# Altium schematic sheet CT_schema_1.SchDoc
size 576 x 540 mm
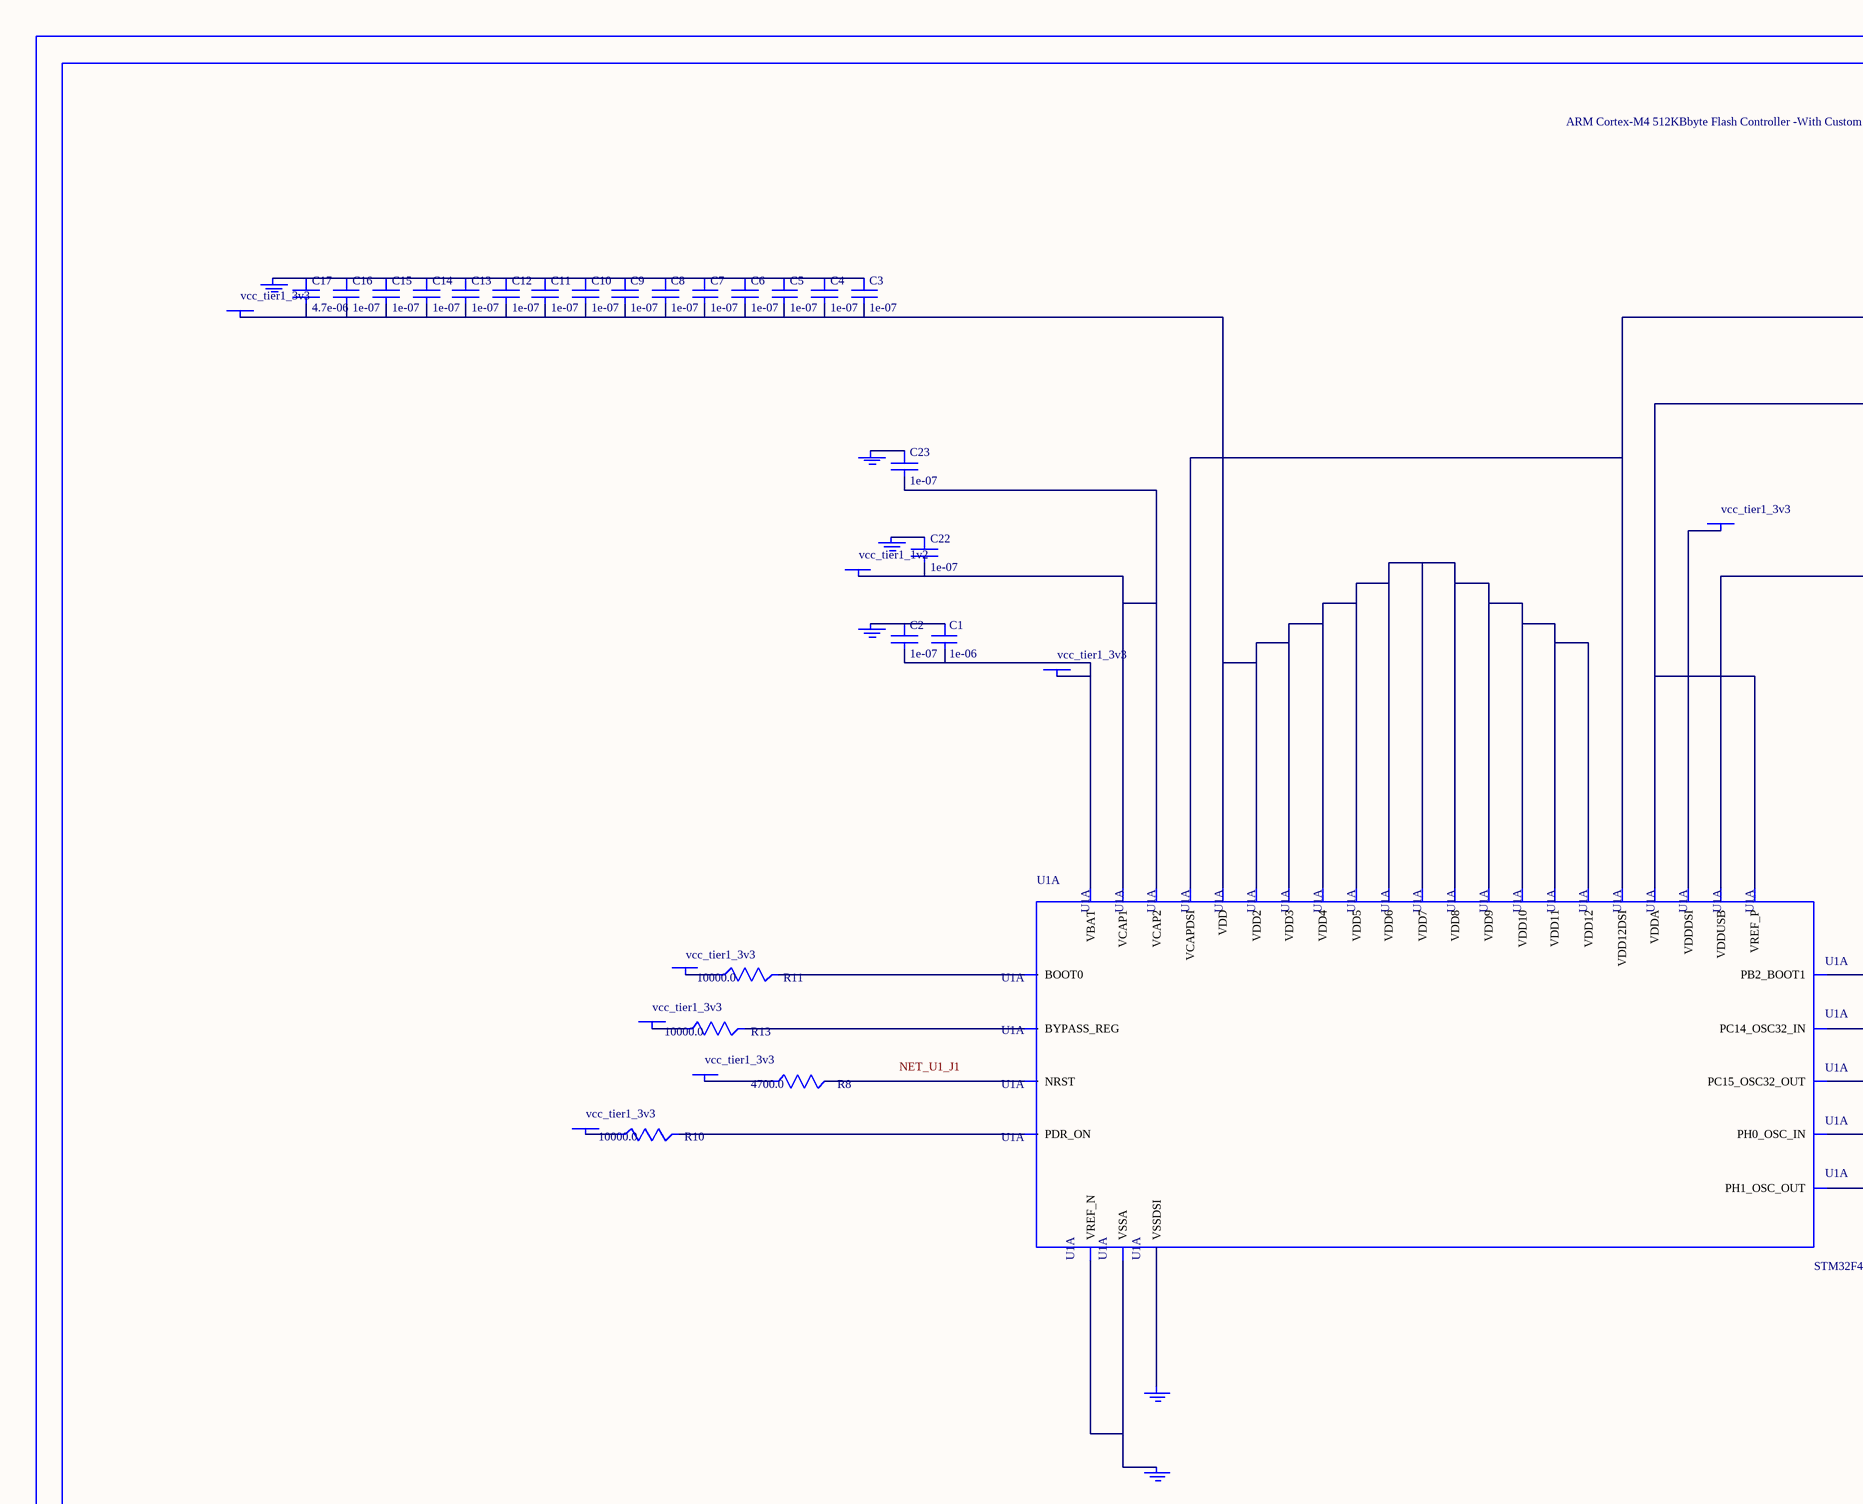
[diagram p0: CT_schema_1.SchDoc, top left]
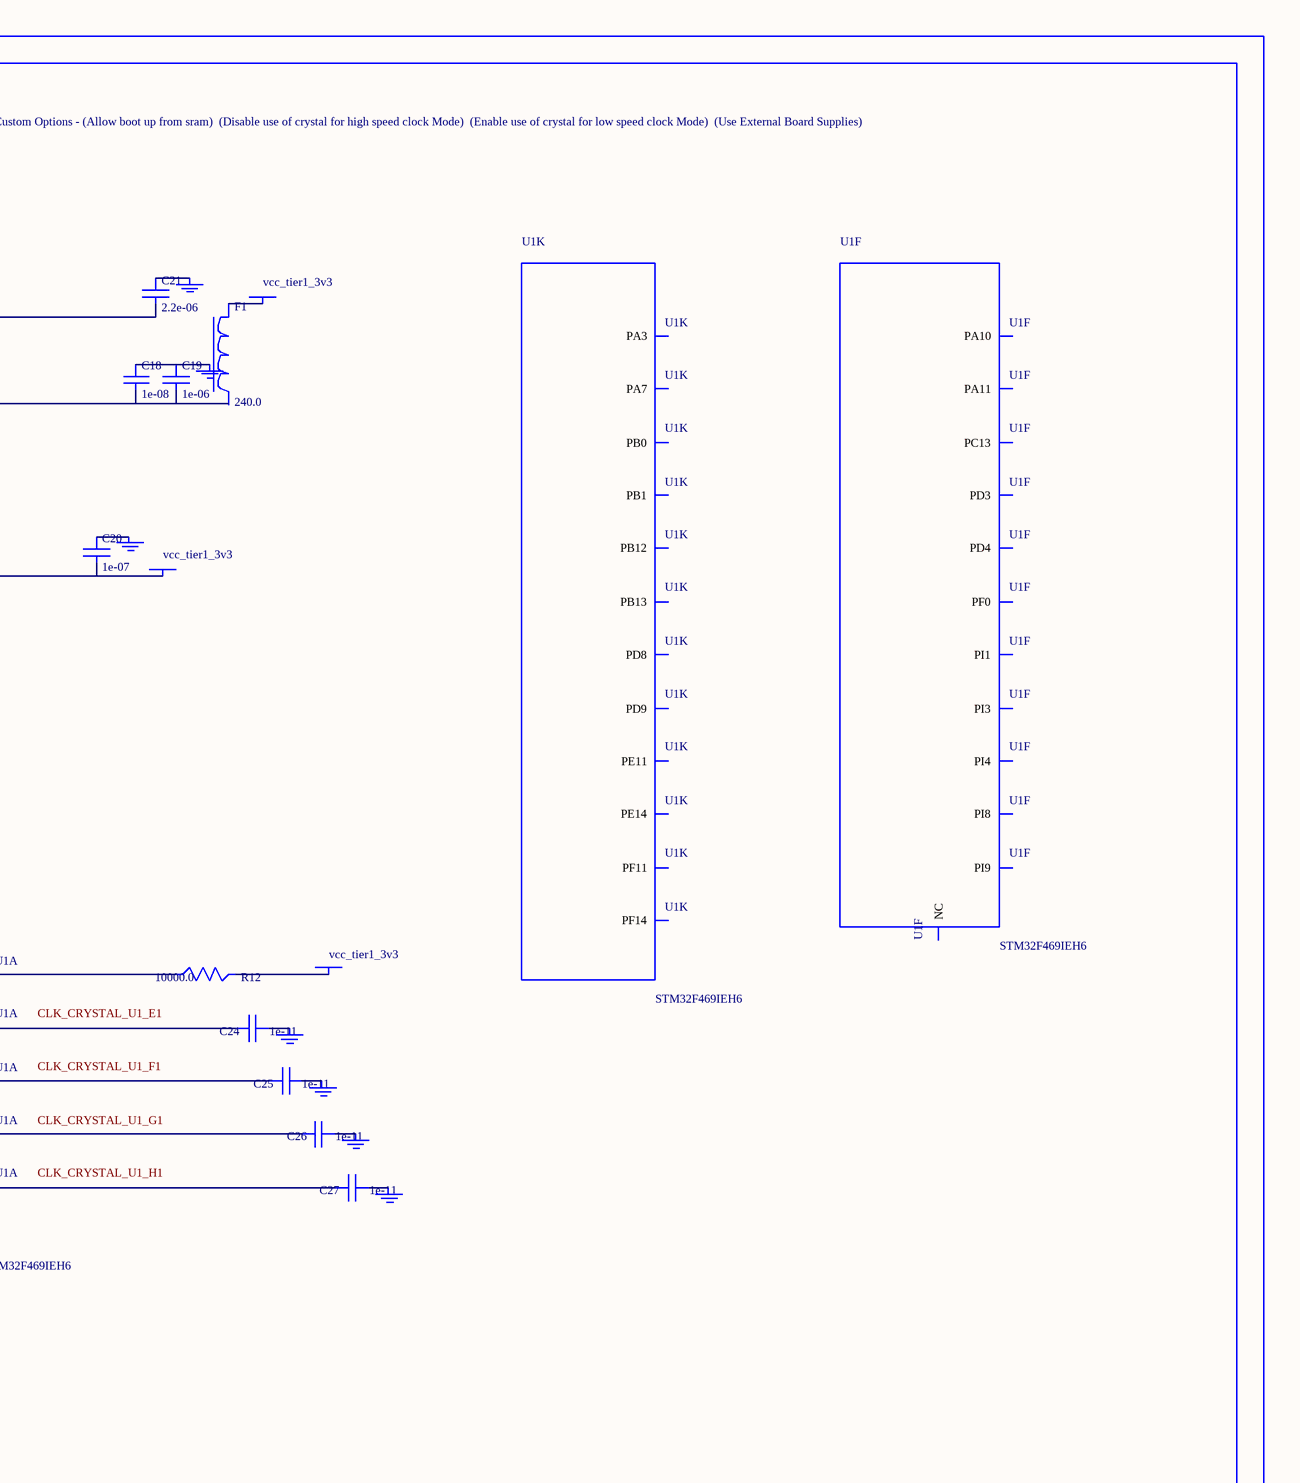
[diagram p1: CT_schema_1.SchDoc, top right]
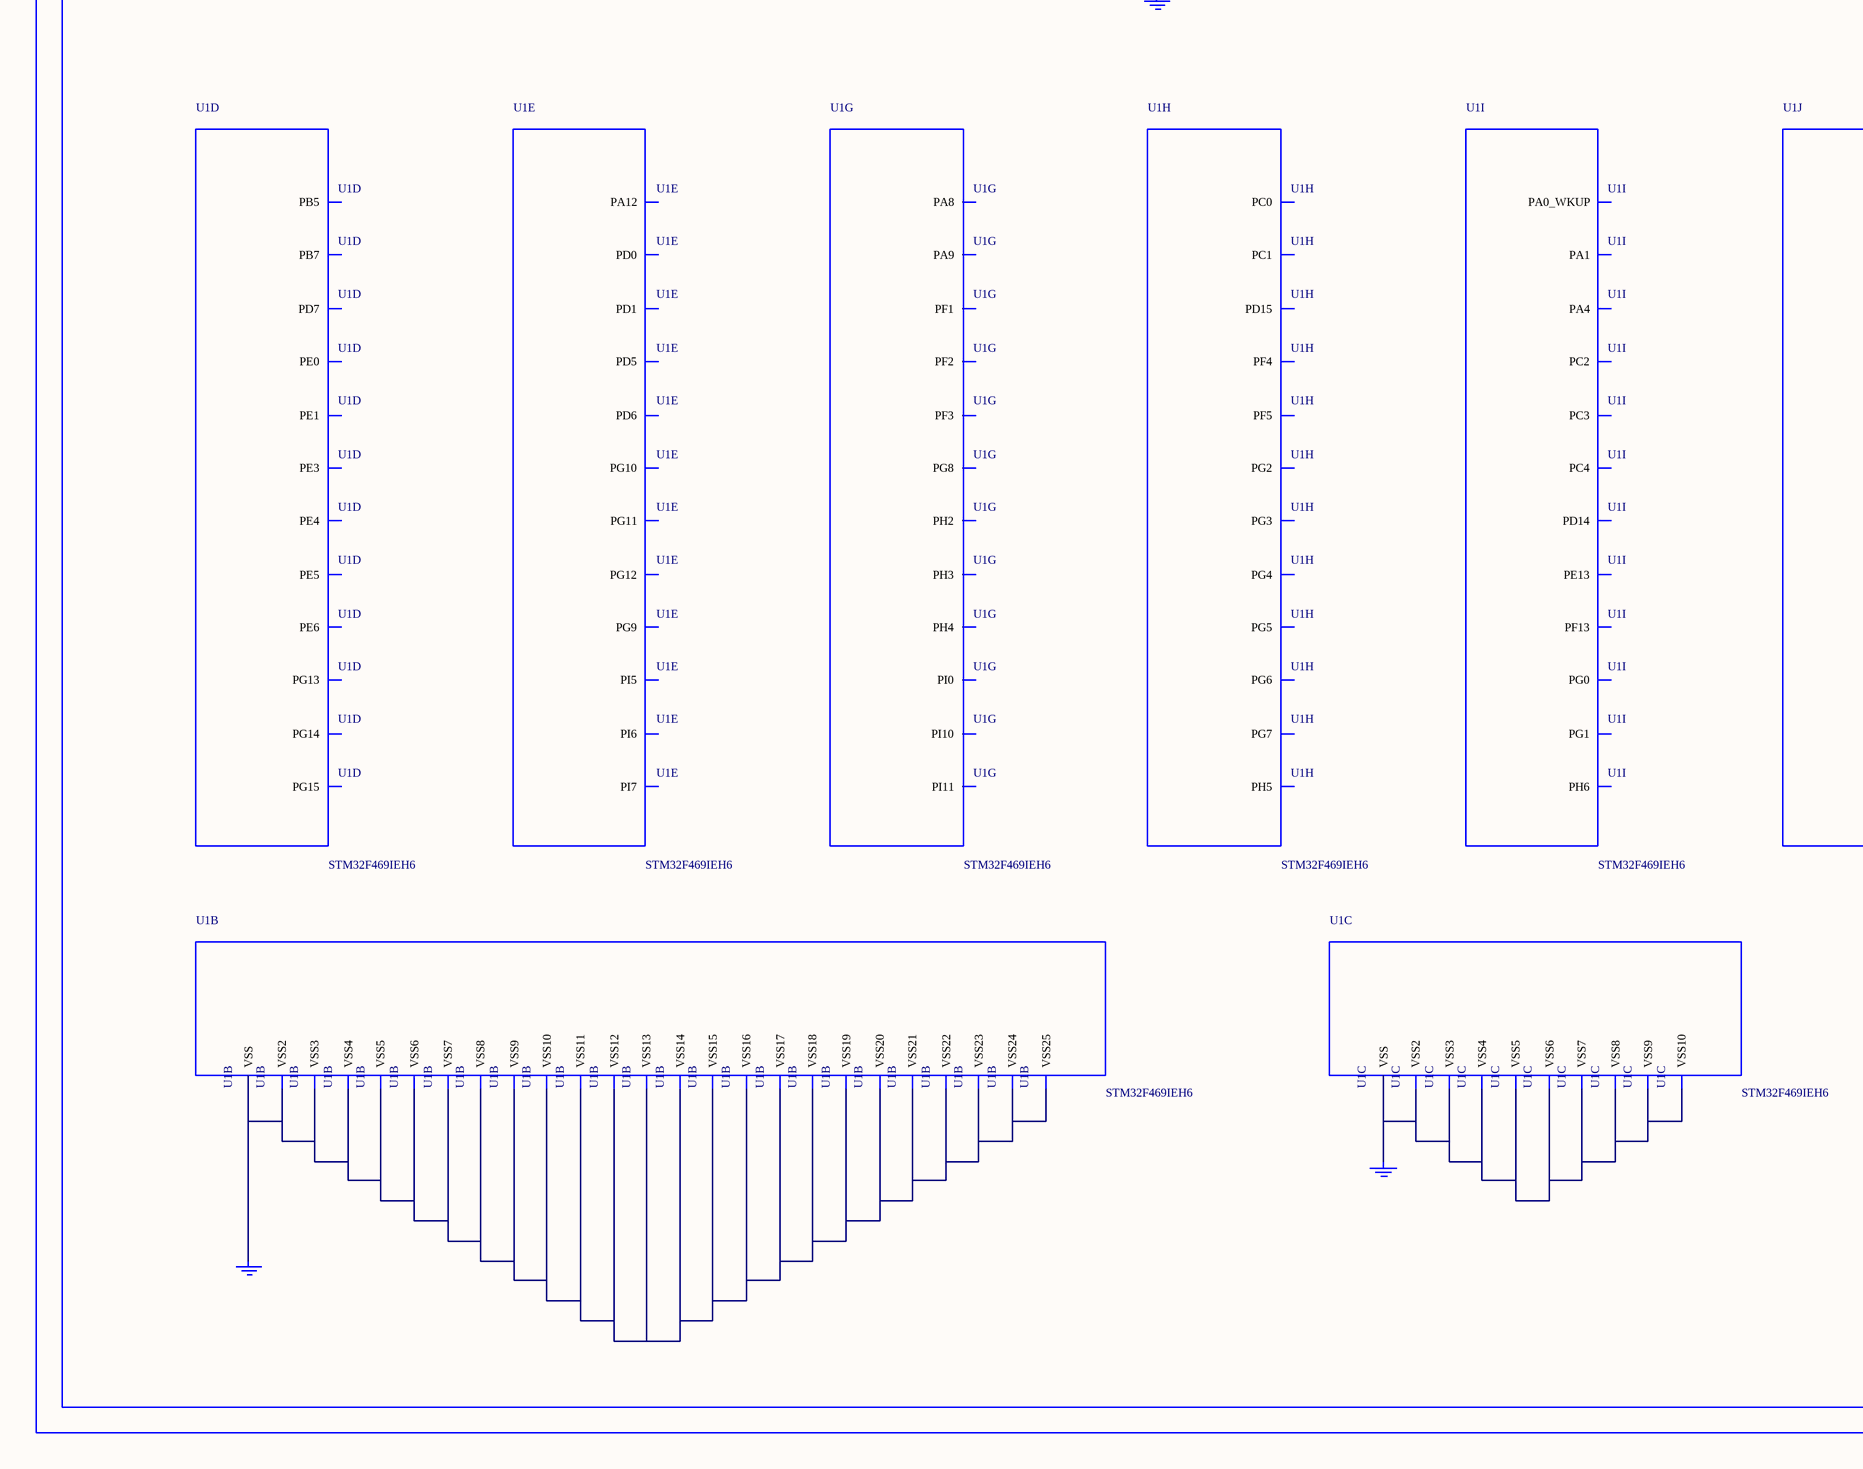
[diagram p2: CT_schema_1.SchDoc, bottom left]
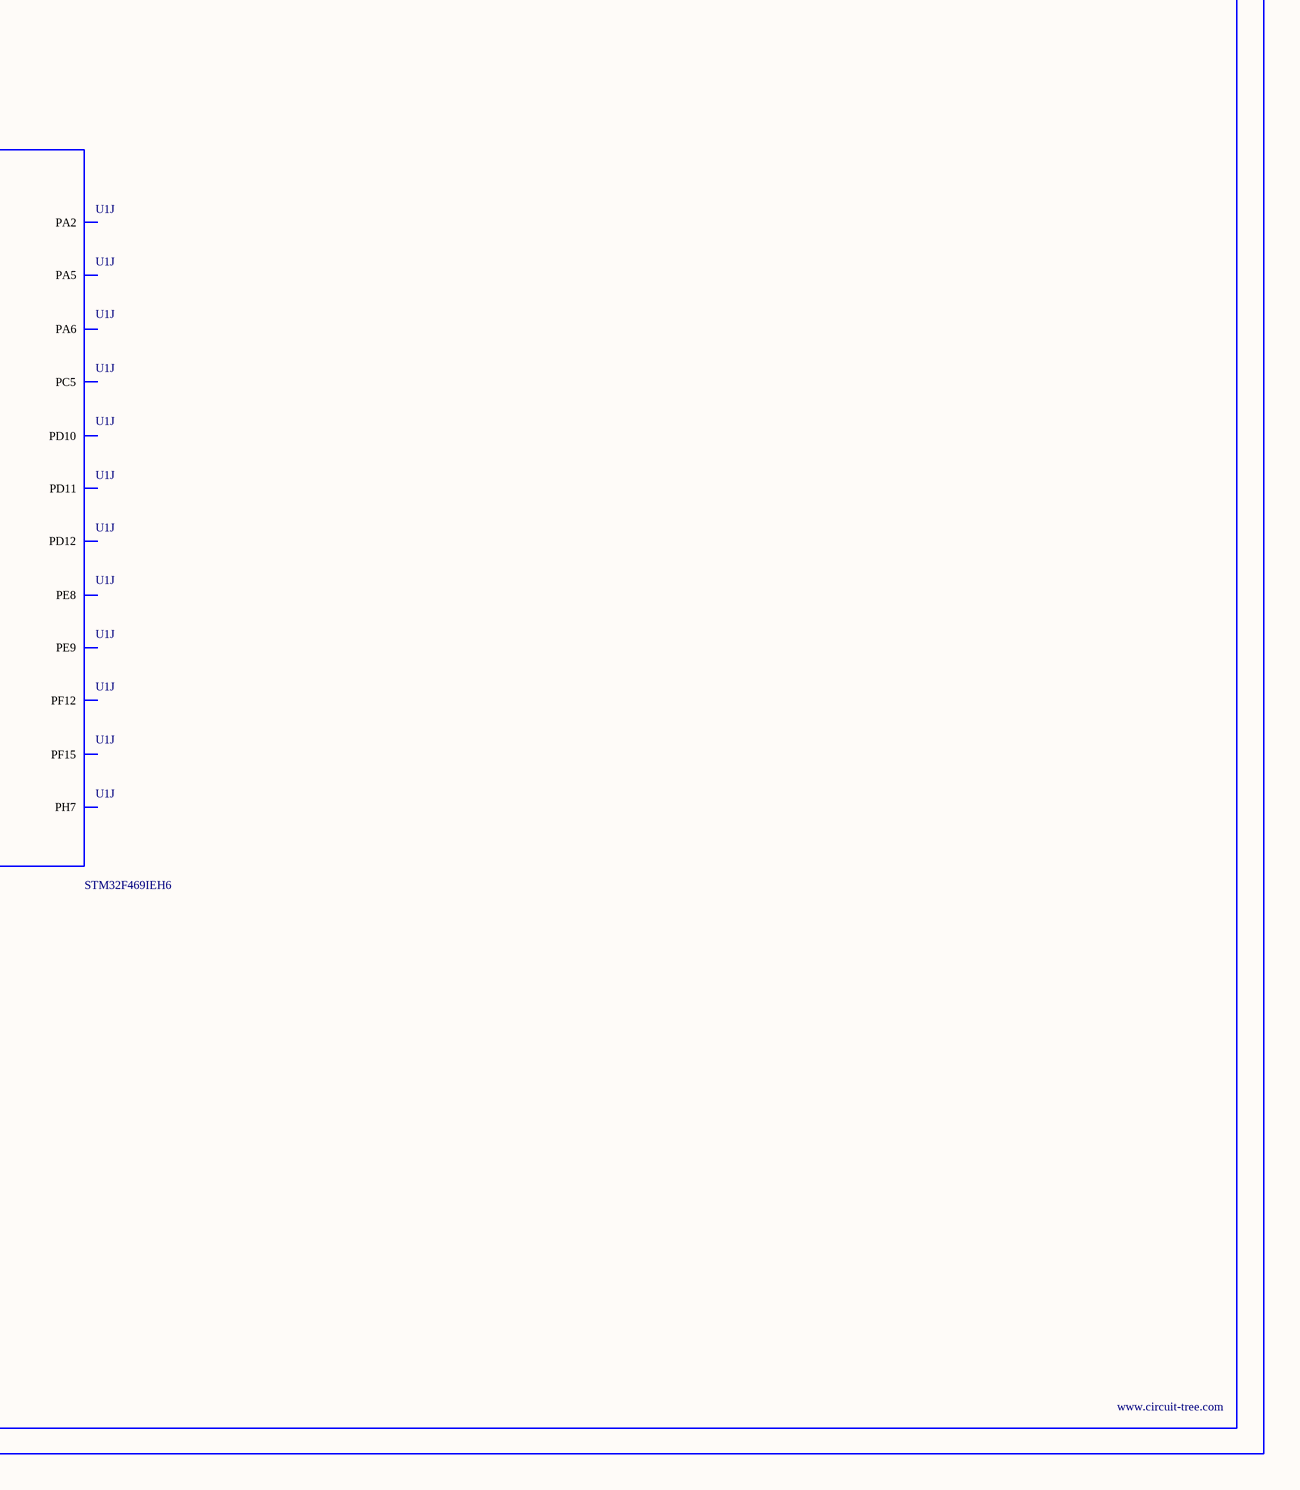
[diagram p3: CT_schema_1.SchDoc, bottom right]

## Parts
BORDER0  (no value)
C1  1e-06  [C0603]
C2  1e-07  [C0603]
C3  1e-07  [C0603]
C4  1e-07  [C0603]
C5  1e-07  [C0603]
C6  1e-07  [C0603]
C7  1e-07  [C0603]
C8  1e-07  [C0603]
C9  1e-07  [C0603]
C10  1e-07  [C0603]
C11  1e-07  [C0603]
C12  1e-07  [C0603]
C13  1e-07  [C0603]
C14  1e-07  [C0603]
C15  1e-07  [C0603]
C16  1e-07  [C0603]
C17  4.7e-06  [C0603]
C18  1e-08  [C0603]
C19  1e-06  [C0603]
C20  1e-07  [C0603]
C21  2.2e-06  [C0603]
C22  1e-07  [C0603]
C23  1e-07  [C0603]
C24  1e-11  [C0402]
C25  1e-11  [C0402]
C26  1e-11  [C0402]
C27  1e-11  [C0402]
F1  240.0  [L0603]
GND_INSTANCE_0_0  (no value)
GND_INSTANCE_0_1  (no value)
GND_INSTANCE_0_2  (no value)
GND_INSTANCE_0_3  (no value)
GND_INSTANCE_0_4  (no value)
GND_INSTANCE_0_5  (no value)
GND_INSTANCE_0_6  (no value)
GND_INSTANCE_0_7  (no value)
GND_INSTANCE_0_8  (no value)
GND_INSTANCE_0_9  (no value)
GND_INSTANCE_0_10  (no value)
GND_INSTANCE_0_11  (no value)
GND_INSTANCE_0_12  (no value)
GND_INSTANCE_0_13  (no value)
GND_INSTANCE_0_14  (no value)
POWER_INSTANCE_0_0  vcc_tier1_3v3
POWER_INSTANCE_0_1  vcc_tier1_3v3
POWER_INSTANCE_0_2  vcc_tier1_3v3
POWER_INSTANCE_0_3  vcc_tier1_3v3
POWER_INSTANCE_0_4  vcc_tier1_3v3
POWER_INSTANCE_0_5  vcc_tier1_3v3
POWER_INSTANCE_0_6  vcc_tier1_3v3
POWER_INSTANCE_0_7  vcc_tier1_3v3
POWER_INSTANCE_0_8  vcc_tier1_1v2
POWER_INSTANCE_0_9  vcc_tier1_3v3
POWER_INSTANCE_0_10  vcc_tier1_3v3
R8  4700.0  [R0603]
R10  10000.0  [R0603]
R11  10000.0  [R0603]
R12  10000.0  [R0603]
R13  10000.0  [R0603]
U1  STM32F469IEH6  [UFBGA176]  (parts A,B,C,D,E,F,G,H,I,J,K of 16)

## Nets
NetC1_1: C1.1 C2.1 GND_INSTANCE_0_0.0(GND)
NetC1_2: C1.2 C2.2 POWER_INSTANCE_0_0.0(PWR) U1.C1(VBAT)
NetC3_1: C3.1 C4.1 C5.1 C6.1 C7.1 C8.1 C9.1 C10.1 C11.1 C12.1 C13.1 C14.1 C15.1 C16.1 C17.1 GND_INSTANCE_0_2.0(GND)
NetC3_2: C3.2 C4.2 C5.2 C6.2 C7.2 C8.2 C9.2 C10.2 C11.2 C12.2 C13.2 C14.2 C15.2 C16.2 C17.2 POWER_INSTANCE_0_2.0(PWR) U1.C5(VDD) U1.C7(VDD2) U1.C8(VDD3) U1.C9(VDD4) U1.F3(VDD5) U1.G3(VDD7) U1.G13(VDD6) U1.J13(VDD8) U1.K4(VDD9) U1.N8(VDD11) U1.N9(VDD12) U1.N10(VDD10)
NetC18_1: C18.1 C19.1 GND_INSTANCE_0_1.0(GND)
NetC18_2: C18.2 C19.2 U1.P1(VREF_P) U1.R1(VDDA)
NetC20_1: C20.1 GND_INSTANCE_0_3.0(GND)
NetC20_2: C20.2 POWER_INSTANCE_0_4.0(PWR) U1.H13(VDDUSB)
NetC21_1: C21.1 GND_INSTANCE_0_4.0(GND)
NetC21_2: C21.2 U1.D13(VDD12DSI) U1.K12(VCAPDSI)
NetC22_1: C22.1 GND_INSTANCE_0_5.0(GND)
NetC22_2: C22.2 C23.2 POWER_INSTANCE_0_8.0(PWR) U1.F13(VCAP2) U1.M10(VCAP1)
NetC23_1: C23.1 GND_INSTANCE_0_6.0(GND)
NetC24_1: C24.1 GND_INSTANCE_0_7.0(GND)
NetC24_2: C24.2 U1.E1(PC14_OSC32_IN)
NetC25_1: C25.1 GND_INSTANCE_0_8.0(GND)
NetC25_2: C25.2 U1.F1(PC15_OSC32_OUT)
NetC26_1: C26.1 GND_INSTANCE_0_9.0(GND)
NetC26_2: C26.2 U1.G1(PH0_OSC_IN)
NetC27_1: C27.1 GND_INSTANCE_0_10.0(GND)
NetC27_2: C27.2 U1.H1(PH1_OSC_OUT)
NetF1_1: F1.1 POWER_INSTANCE_0_1.0(PWR)
NetGND_INSTANCE_0_11_0: GND_INSTANCE_0_11.0(GND) U1.M1(VSSA) U1.N1(VREF_N)
NetGND_INSTANCE_0_12_0: GND_INSTANCE_0_12.0(GND) U1.H12(VSSDSI)
NetGND_INSTANCE_0_13_0: GND_INSTANCE_0_13.0(GND) U1.D5(VSS) U1.D7(VSS2) U1.D8(VSS3) U1.D9(VSS4) U1.F2(VSS7) U1.F6(VSS8) U1.F7(VSS9) U1.F8(VSS10) U1.F9(VSS11) U1.F10(VSS5) U1.F12(VSS6) U1.G2(VSS14) U1.G6(VSS15) U1.G7(VSS16) U1.G8(VSS17) U1.G9(VSS18) U1.G10(VSS12) U1.G12(VSS13) U1.H6(VSS20) U1.H7(VSS21) U1.H8(VSS22) U1.H9(VSS23) U1.H10(VSS19) U1.J6(VSS25) U1.J10(VSS24)
NetGND_INSTANCE_0_14_0: GND_INSTANCE_0_14.0(GND) U1.J7(VSS) U1.J8(VSS2) U1.J9(VSS3) U1.K6(VSS5) U1.K7(VSS6) U1.K8(VSS7) U1.K9(VSS8) U1.K10(VSS4) U1.M8(VSS9) U1.M9(VSS10)
NetPOWER_INSTANCE_0_3_0: POWER_INSTANCE_0_3.0(PWR) R10.1
NetPOWER_INSTANCE_0_5_0: POWER_INSTANCE_0_5.0(PWR) R11.1
NetPOWER_INSTANCE_0_6_0: POWER_INSTANCE_0_6.0(PWR) R12.2
NetPOWER_INSTANCE_0_7_0: POWER_INSTANCE_0_7.0(PWR) R13.1
NetPOWER_INSTANCE_0_9_0: POWER_INSTANCE_0_9.0(PWR) U1.J12(VDDDSI)
NetPOWER_INSTANCE_0_10_0: POWER_INSTANCE_0_10.0(PWR) R8.1
NetR8_2: R8.2 U1.J1(NRST)
NetR10_2: R10.2 U1.C6(PDR_ON)
NetR11_2: R11.2 U1.D6(BOOT0)
NetR12_1: R12.1 U1.M6(PB2_BOOT1)
NetR13_2: R13.2 U1.L4(BYPASS_REG)

Not connected (* = marked no-connect by the designer): F1 2; U1 A1(PE3) A3(PE1) A4(PE0) A6(PB5) A7(PG14) A8(PG13) A11(PD7) B1(PE4) B2(PE5) B3(PE6) B5(PB7) B7(PG15) B8(PG12) B9(PG11) B10(PG10) B11(PD6) B12(PD0) B15(PA12) C2(PI7) C3(PI6) C4(PI5) C10(PG9) C11(PD5) C12(PD1) C13(PI3) C14(NC) C15(PA11) D1(PC13) D2(PI8) D3(PI9) D4(PI4) D10(PD4) D11(PD3) D14(PI1) D15(PA10) E2(PF0) E3(PI10) E4(PI11) E14(PI0) E15(PA9) F4(PH2) F15(PA8) G4(PH3) H2(PF2) H3(PF1) H4(PH4) H14(PG8) J2(PF3) J3(PF4) J4(PH5) J14(PG7) J15(PG6) K3(PF5) K13(PG5) K14(PG4) K15(PG3) L14(PD15) L15(PG2) M2(PC0) M3(PC1) M4(PC2) M5(PC3) M7(PG1) M11(PH6) M14(PD14) N2(PA1) N3(PA0_WKUP) N4(PA4) N5(PC4) N6(PF13) N7(PG0) N11(PE13) N12(PH7) N13(PD12) N14(PD11) N15(PD10) P2(PA2) P3(PA6) P4(PA5) P5(PC5) P6(PF12) P7(PF15) P8(PE8) P9(PE9) P10(PE11) P11(PE14) P12(PB12) P13(PB13) P14(PD9) P15(PD8) R2(PA3) R3(PA7) R4(PB1) R5(PB0) R6(PF11) R7(PF14)

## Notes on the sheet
- Labels drawn without touching a wire or pin: CLK_CRYSTAL_U1_E1, CLK_CRYSTAL_U1_F1, CLK_CRYSTAL_U1_G1, CLK_CRYSTAL_U1_H1, NET_U1_J1

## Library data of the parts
BORDER0 = BORDER_PAGE0
C1 C19 = C0603C105K3RACTU
C2-C16 C20 C22 C23 = 06035C104K4Z2A
C17 = GRM188R6YA475KE15D
C18 = 06035C103K4Z2A
C21 = C0603C225K8RACTU
C24-C27 = C0402C100K3GACTU
F1 = Z0603C241ASMST
GND_INSTANCE_0_0-GND_INSTANCE_0_14 = GND
POWER_INSTANCE_0_0-POWER_INSTANCE_0_10 = PWR
R8 = RC0603JR-074K7L
R10-R13 = RC0603JR-0710KL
